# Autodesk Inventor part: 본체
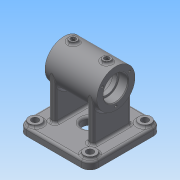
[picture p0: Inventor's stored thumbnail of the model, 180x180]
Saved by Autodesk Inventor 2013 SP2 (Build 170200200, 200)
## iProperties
Created: 2025-10
Part Number: 본체
Material: Generic
Document SubType Name: Modeling
Designer: 601
Density: 1 g/cm^3
Mass: 186.6 g
Surface Area: 499.366 cm^2
Volume: 186.6 cm^3
Author: 601
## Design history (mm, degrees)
sketch "스케치1"
  geometry: L1 (47, -47)-(-47, -47); L2 (-47, -47)-(-47, 47); L3 (-47, 47)-(47, 47); L4 (47, 47)-(47, -47); L5 (47, -47)-(-47, 47); L6 (-47, -47)-(47, 47); L7 (-21, 22)-(-21, -22); L8 (-29, 22)-(-29, -22); L9 (0, -47)-(0, 47); L10 (21, 22)-(21, -22); L11 (29, 22)-(29, -22); L12 (-26, 25)-(-24, 25); L13 (24, 25)-(26, 25); L14 (24, -25)-(26, -25); L15 (-26, -25)-(-24, -25); C1 r 10 at (0, 0); A1 r 3 centre (-26, 22) between (-26, 25) and (-29, 22); A2 r 3 centre (-24, 22) between (-21, 22) and (-24, 25); A3 r 3 centre (-26, -22) between (-29, -22) and (-26, -25); A4 r 3 centre (-24, -22) between (-24, -25) and (-21, -22); A5 r 3 centre (24, -22) between (21, -22) and (24, -25); A6 r 3 centre (26, -22) between (26, -25) and (29, -22); A7 r 3 centre (26, 22) between (29, 22) and (26, 25); A8 r 3 centre (24, 22) between (24, 25) and (21, 22); 9 further points
  constraints: 30 end point, 16 point on circle, 16 point on line, 16 tangent, 9 centre point, 6 equal radius, 6 midpoint, 5 parallel, 4 symmetric about line, 2 perpendicular, 1 collinear, 1 horizontal
  dimensions: "d0" = 94 distance of L2.end L3.end; "d1" = 94 distance of L3.end L1.start; "d67" = 20 diameter of C1; "d150" = 25 distance from line of L12 point (0, 0); "d151" = 8 distance of point (-29, 25) point (-21, 25); "d152" = 42 distance between parallel lines of L7 L10; "d153" = 3 radius of A1; "d154" = 50 distance between parallel lines of L15 L12; "d155" = 3 radius of A3
extrude "돌출1" new body sketch "스케치1" distance "d7" = 10; taper "d8" = 0 deg
sketch "스케치2"
  geometry: L1 (-47, 0)-(-47, 10) reference; L2 (-47, 10)-(47, 10) reference; L3 (47, 10)-(47, 0) reference; L4 (47, 0)-(-47, 0) reference; L5 (-34, 66)-(34, 66); L6 (-34, 66)-(-34, 50); L7 (-34, 41)-(34, 41); L8 (34, 41)-(34, 50); L9 (-34, 50)-(-22.3, 50); L10 (-22, 50.3)-(-22, 52.5); L11 (-22, 52.5)-(-16.258, 52.5); L12 (-16.258, 52.5)-(-5.696, 46.402); L13 (-4.196, 46)-(4.196, 46); L14 (5.696, 46.402)-(16.258, 52.5); L15 (16.258, 52.5)-(22, 52.5); L16 (22, 52.5)-(22, 50.3); L17 (22.3, 50)-(34, 50); L18 (-34, 50)-(-34, 41); L19 (34, 50)-(34, 66); A1 r 0.3 centre (-22.3, 50.3) between (-22.3, 50) and (-22, 50.3); A2 r 0.3 centre (22.3, 50.3) between (22, 50.3) and (22.3, 50); A3 r 3 centre (-4.196, 49) between (-5.696, 46.402) and (-4.196, 46); A4 r 3 centre (4.196, 49) between (4.196, 46) and (5.696, 46.402); 8 further points
  constraints: 30 end point, 8 point on circle, 8 point on line, 8 tangent, 7 perpendicular, 6 parallel, 4 centre point, 4 vertical alignment, 3 midpoint, 2 equal radius
  dimensions: "d9" = 66 vertical distance of L3.end L5.end; "d10" = 68 distance of L5.start L5.end; "d11" = 50 diameter of L7 L5; "d12" = 12 distance of L6.end point (-22, 50); "d13" = 12 distance of point (22, 50) L8.end; "d14" = 10 distance of point (-5, 46) point (5, 46); "d15" = 30 deg angle of L5 L12; "d16" = 30 deg angle of L5 L14; "d17" = 32 diameter of L9 L5; "d18" = 27 diameter of L11 L5; "d19" = 40 diameter of L13 L5; "d20" = 32 diameter of L17 L5; "d22" = 27 diameter of L15 L5; "d23" = 0.3 radius of A1; "d24" = 3 radius of A3
revolve "회전1" sketch "스케치2" stored, may be unused: angle "d25" = 90 deg
extrude "돌출2" join sketch "스케치1" stored distance "d26" = 66.25; taper "d27" = 0 deg
node "작업 평면1"
sketch "스케치3"
  geometry: L1 (34, -25)-(34, 25) reference; L2 (-34, -25)-(-34, 25) reference; C1 r 5 at (-22, 0); C2 r 5 at (22, 0); 1 further point
  constraints: 2 centre point, 2 horizontal alignment
  dimensions: "d29" = 10 diameter of C1; "d30" = 10 diameter of C2; "d31" = 12 distance from line of C2.centre L1; "d32" = 12 distance from line of C1.centre L2
extrude "돌출3" join sketch "스케치3" stored distance "d33" = 66.25; taper "d34" = 0 deg
hole "구멍1" diameter "d37" = 5.188; stored, may be unused: countersink angle "d41" = 90 deg, drill point angle "d43" = 0 deg; dims "d35" = 10, "d36" = 10, "d38" = 6, "d39" = 6.6, "d40" = 2, "d42" = 8
hole "구멍2" diameter "d46" = 5.188; stored, may be unused: countersink angle "d50" = 90 deg, drill point angle "d52" = 0 deg; dims "d44" = 10, "d45" = 10, "d47" = 6, "d48" = 6.6, "d49" = 2, "d51" = 8
extrude "돌출4" cut sketch "스케치1" distance "d68" = 10; taper "d69" = 0 deg
fillet "모깎기1" dims "d70" = 11
sketch "스케치5"
  geometry: C1 r 8 at (-36, 36); C2 r 8 at (36, 36); C3 r 8 at (36, -36); C4 r 8 at (-36, -36); A1 r 11 centre (-36, 36) between (-36, 47) and (-47, 36) reference; A2 r 11 centre (-36, -36) between (-47, -36) and (-36, -47) reference; A3 r 11 centre (36, -36) between (36, -47) and (47, -36) reference; A4 r 11 centre (36, 36) between (47, 36) and (36, 47) reference
  constraints: 4 centre point, 4 coincident
  dimensions: "d71" = 16 diameter of C1; "d73" = 16 diameter of C2; "d74" = 16 diameter of C3; "d75" = 16 diameter of C4
extrude "돌출5" join sketch "스케치5" distance "d76" = 3; taper "d77" = 0 deg
hole "구멍4" diameter "d80" = 9; stored, may be unused: countersink angle "d84" = 90 deg, drill point angle "d86" = 0 deg; dims "d78" = 10, "d79" = 10, "d81" = 6, "d82" = 4, "d83" = 2, "d85" = 8
hole "구멍5" diameter "d89" = 9; stored, may be unused: countersink angle "d93" = 90 deg, drill point angle "d95" = 0 deg; dims "d87" = 10, "d88" = 10, "d90" = 6, "d91" = 4, "d92" = 2, "d94" = 8
hole "구멍6" diameter "d98" = 9; stored, may be unused: countersink angle "d102" = 90 deg, drill point angle "d104" = 0 deg; dims "d96" = 10, "d97" = 10, "d99" = 6, "d100" = 4, "d101" = 2, "d103" = 8
hole "구멍7" diameter "d107" = 9; stored, may be unused: countersink angle "d111" = 90 deg, drill point angle "d113" = 0 deg; dims "d105" = 10, "d106" = 10, "d108" = 6, "d109" = 4, "d110" = 2, "d112" = 8
node "작업 평면3"
sketch "스케치6"
  geometry: L1 (-21.79, 2.742)-(21.79, 2.742); L2 (21.79, 2.742)-(21.79, -2.742); L3 (21.79, -2.742)-(-21.79, -2.742); L4 (-21.79, -2.742)-(-21.79, 2.742); L5 (36, -66)-(-36, -66) reference; L6 (34, -25)-(34, 25) reference; 5 further points
  constraints: 4 midpoint, 1 horizontal alignment, 1 vertical alignment, 2 other
feature "엠보싱1" sketch "스케치6" dims "d0" = 94, "d1" = 94, "d9" = 66, "d10" = 68, "d11" = 50, "d12" = 12, "d13" = 12, "d14" = 10, "d15" = 30 deg, "d16" = 30 deg, "d17" = 32, "d18" = 27, "d19" = 40, "d20" = 32, "d22" = 27, "d23" = 0.3, "d24" = 3, "d67" = 20, "d114" = 0.5, "d115" = 0, "d150" = 25, "d151" = 8, "d152" = 42, "d153" = 3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
chamfer "모따기1" distance "d116" = 1; stored, may be unused: second distance "d117" = 2, angle "d118" = 45 deg
fillet "모깎기2" dims "d119" = 3
fillet "모깎기3" dims "d120" = 3
fillet "모깎기4" dims "d121" = 3
node "작업 평면4"
sketch "스케치7"
  geometry: C1 r 6 at (0, 0); 1 further point
  constraints: 1 centre point, 1 coincident
  dimensions: "d123" = 12 diameter of C1
extrude "돌출6" join sketch "스케치7" stored distance "d124" = 3; taper "d125" = 0 deg
hole "구멍8" diameter "d128" = 5.188; stored, may be unused: countersink angle "d132" = 90 deg, drill point angle "d134" = 0 deg; dims "d126" = 10, "d127" = 10, "d129" = 6, "d130" = 4, "d131" = 2, "d133" = 8
sketch "스케치8"
  geometry: L1 (0, 0)-(0, 20.5); L2 (0, 0)-(-17.754, 10.25); C1 r 17 at (0, 0) reference; A1 r 20.5 centre (0, 0) between (0, 20.5) and (-17.754, 10.25); 2 further points
  constraints: 4 end point, 2 coincident, 2 point on circle, 1 centre point, 1 vertical
  dimensions: "d135" = 41 diameter of A1; "d136" = 60 deg angle of L2 L1
hole "구멍9" sketch "스케치8" at (-17.754, 10.25) diameter "d138" = 3.242; stored, may be unused: countersink angle "d142" = 90 deg, drill point angle "d144" = 118 deg; dims "d139" = 8, "d140" = 4, "d141" = 2, "d143" = 10
fillet "모깎기5" dims "d148" = 3
fillet "모깎기6" dims "d156" = 3
node "솔리드1"
pattern_circular "원형 패턴1" dims angle "d146" = 360 deg
mirror "대칭1"
node "절단 모서리 투영1"
other parameters: "d28" = 94, "d122" = 38
